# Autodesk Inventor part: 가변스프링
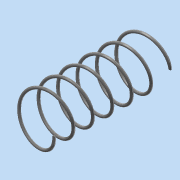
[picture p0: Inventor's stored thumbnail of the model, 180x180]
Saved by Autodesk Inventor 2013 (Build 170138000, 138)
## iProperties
Created: 2016-11
Part Number: 가변스프링
Material: 강철, 탄소
Document SubType Name: Modeling
Designer: Administrator
Mass: 14.8212 g
Surface Area: 38.0291 cm^2
Volume: 1.88326 cm^3
Density: 7.87 g/cm^3
Author: Administrator
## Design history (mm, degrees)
sketch "스케치1"
  geometry: L1 (0, 0)-(16, 0); L2 (16, 0)-(16, 84.368); L3 (16, 84.368)-(0, 84.368); L4 (0, 84.368)-(0, 0); C1 r 1 at (16, 0)
  constraints: 8 end point, 2 parallel, 1 centre point, 1 coincident, 1 horizontal, 1 perpendicular
  dimensions: "d0" = 32 diameter of L2 L4; "d2" = 84.36759 distance between parallel lines of L1 L3 (derived); "d3" = 2 diameter of C1
feature "코일1" sketch "스케치1" pitch "d4" = 10; turns "d6" = 6; dims "d5" = 84.36759 (= d2), "d7" = 0, angle "d8" = 90 deg, angle "d9" = 90 deg, "d10" = 0, "d11" = 0
feature "분할1"
node "작업 평면1"
feature "분할2"
node "솔리드1"
other parameters: "d12" = 90 deg
